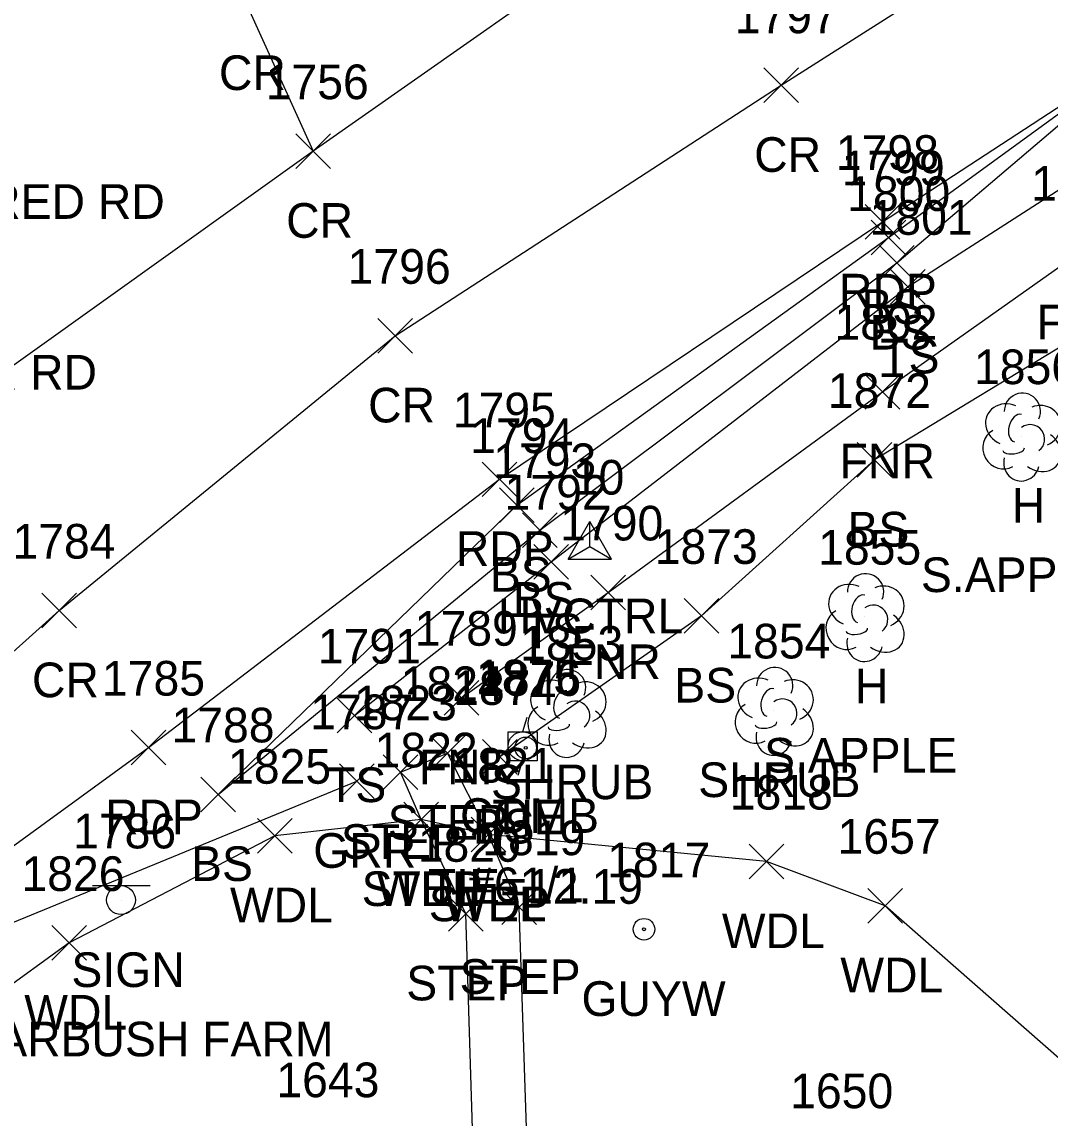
# Model space of a CAD drawing. Extents: x 1647133 to 1649138, y 411736 to 414924.
# Drawn here: x 1649009.1 to 1649068.5, y 412216.1 to 412279.3 of the extents above; entities that cross this region are included whole.
import ezdxf

# ---------------------------------------------------------------- set-up
doc = ezdxf.new("R2010")
doc.units = 0
for name, color, linetype in [('C_A', 7, 'Continuous'), ('C_C', 7, 'Continuous'), ('C_I', 7, 'Continuous'), ('CBP', 7, 'Continuous'), ('CPSM', 7, 'Continuous'), ('L_A', 7, 'Continuous'), ('L_C', 7, 'Continuous'), ('L_I', 7, 'Continuous'), ('L_TIC', 7, 'Continuous'), ('LAWA', 7, 'Continuous'), ('LBF', 7, 'Continuous'), ('LELB', 7, 'Continuous'), ('LFNC', 7, 'Continuous'), ('LSH', 7, 'Continuous'), ('LTD', 7, 'Continuous'), ('P_A', 7, 'Continuous'), ('P_I', 7, 'Continuous'), ('P_TIC', 7, 'Continuous'), ('PET', 7, 'Continuous'), ('PRC', 7, 'Continuous'), ('R_A', 7, 'Continuous'), ('R_I', 7, 'Continuous'), ('R_TIC', 7, 'Continuous'), ('RGR', 7, 'Continuous'), ('S_A', 7, 'Continuous'), ('S_C', 7, 'Continuous'), ('S_I', 7, 'Continuous'), ('SSGN', 7, 'Continuous'), ('U_A', 7, 'Continuous'), ('U_C', 7, 'Continuous'), ('U_I', 7, 'Continuous'), ('UP', 7, 'Continuous'), ('UPGW', 7, 'Continuous')]:
    doc.layers.add(name, color=color, linetype=linetype)

msp = doc.modelspace()

# ---------------------------------------------------------------- linework, layer by layer
at = {"layer": 'CBP'}
for radius in [0.625, 0.0833]:
    msp.add_circle((1649038.192, 412237.421), radius, dxfattribs=at)
at = {"layer": 'CPSM'}
for p, q in [((1649040.642, 412248.315), (1649041.892, 412250.48)), ((1649040.642, 412248.315), (1649041.892, 412250.48)), ((1649040.642, 412248.315), (1649041.892, 412250.48)), ((1649040.642, 412248.315), (1649041.892, 412250.48)), ((1649040.642, 412248.315), (1649041.892, 412250.48)), ((1649043.142, 412248.315), (1649041.892, 412250.48)), ((1649041.892, 412249.036), (1649041.892, 412250.48)), ((1649043.142, 412248.315), (1649041.892, 412250.48)), ((1649041.892, 412249.036), (1649041.892, 412250.48)), ((1649043.142, 412248.315), (1649041.892, 412250.48)), ((1649041.892, 412249.036), (1649041.892, 412250.48)), ((1649043.142, 412248.315), (1649041.892, 412250.48)), ((1649041.892, 412249.036), (1649041.892, 412250.48)), ((1649043.142, 412248.315), (1649041.892, 412250.48)), ((1649041.892, 412249.036), (1649041.892, 412250.48)), ((1649040.642, 412248.315), (1649041.892, 412249.036)), ((1649040.642, 412248.315), (1649041.892, 412249.036)), ((1649040.642, 412248.315), (1649041.892, 412249.036)), ((1649040.642, 412248.315), (1649041.892, 412249.036)), ((1649040.642, 412248.315), (1649041.892, 412249.036)), ((1649041.892, 412249.036), (1649041.892, 412249.036)), ((1649041.892, 412249.036), (1649043.142, 412248.315)), ((1649041.892, 412249.036), (1649041.892, 412249.036)), ((1649041.892, 412249.036), (1649043.142, 412248.315)), ((1649041.892, 412249.036), (1649041.892, 412249.036)), ((1649041.892, 412249.036), (1649043.142, 412248.315)), ((1649041.892, 412249.036), (1649041.892, 412249.036)), ((1649041.892, 412249.036), (1649043.142, 412248.315)), ((1649041.892, 412249.036), (1649041.892, 412249.036)), ((1649041.892, 412249.036), (1649043.142, 412248.315)), ((1649040.642, 412248.315), (1649043.142, 412248.315)), ((1649040.642, 412248.315), (1649043.142, 412248.315)), ((1649040.642, 412248.315), (1649043.142, 412248.315)), ((1649040.642, 412248.315), (1649043.142, 412248.315)), ((1649040.642, 412248.315), (1649043.142, 412248.315))]:
    msp.add_line(p, q, dxfattribs=at)
at = {"layer": 'L_TIC'}
for points in [[(1649058.127, 412265.88), (1649060.127, 412267.88)], [(1649060.127, 412265.88), (1649058.127, 412267.88)], [(1649058.603, 412264.407), (1649060.603, 412266.407)], [(1649060.603, 412264.407), (1649058.603, 412266.407)], [(1649059.245, 412263.03), (1649061.245, 412265.03)], [(1649061.245, 412263.03), (1649059.245, 412265.03)], [(1649057.778, 412256.973), (1649059.778, 412258.973)], [(1649059.778, 412256.973), (1649057.778, 412258.973)], [(1649057.324, 412253.04), (1649059.324, 412255.04)], [(1649059.324, 412253.04), (1649057.324, 412255.04)], [(1649036.681, 412250.434), (1649038.681, 412252.434)], [(1649038.681, 412250.434), (1649036.681, 412252.434)], [(1649038.003, 412248.987), (1649040.003, 412250.987)], [(1649040.003, 412248.987), (1649038.003, 412250.987)], [(1649038.666, 412247.165), (1649040.666, 412249.165)], [(1649040.666, 412247.165), (1649038.666, 412249.165)], [(1649041.96, 412245.39), (1649043.96, 412247.39)], [(1649043.96, 412245.39), (1649041.96, 412247.39)], [(1649047.329, 412244.036), (1649049.329, 412246.036)], [(1649049.329, 412244.036), (1649047.329, 412246.036)], [(1649033.487, 412239.315), (1649035.487, 412241.315)], [(1649035.487, 412239.315), (1649033.487, 412241.315)], [(1649027.319, 412238.289), (1649029.319, 412240.289)], [(1649029.319, 412238.289), (1649027.319, 412240.289)], [(1649032.671, 412236.119), (1649034.671, 412238.119)], [(1649034.671, 412236.119), (1649032.671, 412238.119)], [(1649032.671, 412236.119), (1649034.671, 412238.119)], [(1649034.671, 412236.119), (1649032.671, 412238.119)], [(1649035.698, 412235.9), (1649037.698, 412237.9)], [(1649037.698, 412235.9), (1649035.698, 412237.9)], [(1649029.965, 412235.013), (1649031.965, 412237.013)], [(1649031.965, 412235.013), (1649029.965, 412237.013)], [(1649019.44, 412233.736), (1649021.44, 412235.736)], [(1649021.44, 412233.736), (1649019.44, 412235.736)], [(1649019.44, 412233.736), (1649021.44, 412235.736)], [(1649021.44, 412233.736), (1649019.44, 412235.736)], [(1649031.165, 412232.292), (1649033.165, 412234.292)], [(1649033.165, 412232.292), (1649031.165, 412234.292)], [(1649031.165, 412232.292), (1649033.165, 412234.292)], [(1649033.165, 412232.292), (1649031.165, 412234.292)], [(1649022.706, 412231.35), (1649024.706, 412233.35)], [(1649024.706, 412231.35), (1649022.706, 412233.35)], [(1649035.041, 412231.414), (1649037.041, 412233.414)], [(1649037.041, 412231.414), (1649035.041, 412233.414)], [(1649035.041, 412231.414), (1649037.041, 412233.414)], [(1649037.041, 412231.414), (1649035.041, 412233.414)], [(1649051.095, 412229.86), (1649053.095, 412231.86)], [(1649053.095, 412229.86), (1649051.095, 412231.86)], [(1649036.817, 412227.224), (1649038.817, 412229.224)], [(1649038.817, 412227.224), (1649036.817, 412229.224)], [(1649057.93, 412227.309), (1649059.93, 412229.309)], [(1649059.93, 412227.309), (1649057.93, 412229.309)], [(1649033.74, 412226.846), (1649035.74, 412228.846)], [(1649035.74, 412226.846), (1649033.74, 412228.846)], [(1649010.835, 412225.16), (1649012.835, 412227.16)], [(1649012.835, 412225.16), (1649010.835, 412227.16)]]:
    msp.add_lwpolyline(points, dxfattribs=at)
at = {"layer": 'LAWA'}
msp.add_lwpolyline([(1649111.119, 412178.299), (1649089.042, 412199.035), (1649075.25, 412213.993), (1649058.93, 412228.309), (1649052.095, 412230.86), (1649036.041, 412232.414), (1649032.165, 412233.292), (1649023.706, 412232.35), (1649011.835, 412226.16), (1649003.248, 412219.943), (1648994.704, 412211.046)], dxfattribs=at)
at = {"layer": 'LBF'}
for points in [[(1649035.394, 412205.124), (1649035.268, 412210.483), (1649034.74, 412227.846), (1649032.165, 412233.292), (1649030.965, 412236.013), (1649033.671, 412237.119)], [(1649035.394, 412205.124), (1649038.481, 412205.146), (1649038.43, 412209.721), (1649037.817, 412228.224), (1649036.041, 412232.414), (1649033.671, 412237.119)]]:
    msp.add_lwpolyline(points, dxfattribs=at)
at = {"layer": 'LELB'}
for points in [[(1649020.44, 412234.736), (1649037.681, 412251.434), (1649059.127, 412266.88), (1649074.295, 412277.904)], [(1649020.44, 412234.736), (1649039.003, 412249.987), (1649059.603, 412265.407), (1649074.295, 412277.904)], [(1649028.319, 412239.289), (1649039.666, 412248.165), (1649060.245, 412264.03), (1649074.144, 412272.961), (1649081.145, 412265.519)], [(1649131.201, 412223.069), (1649106.638, 412242.921), (1649089.809, 412258.031), (1649081.131, 412263.74), (1649071.005, 412261.74), (1649058.324, 412254.04), (1649048.329, 412245.036), (1649036.698, 412236.9)]]:
    msp.add_lwpolyline(points, dxfattribs=at)
at = {"layer": 'LFNC'}
msp.add_lwpolyline([(1649034.487, 412240.315), (1649042.96, 412246.39), (1649058.778, 412257.973), (1649070.137, 412265.992), (1649075.318, 412269.647)], dxfattribs=at)
at = {"layer": 'LSH'}
for p, q in [((1649040.563, 412239.458), (1649040.563, 412239.458)), ((1649040.563, 412239.458), (1649040.563, 412239.458)), ((1649052.52, 412239.58), (1649052.52, 412239.58)), ((1649052.52, 412239.58), (1649052.52, 412239.58))]:
    msp.add_line(p, q, dxfattribs=at)
for centre in [(1649040.609, 412240.892), (1649052.567, 412241.014)]:
    msp.add_arc(centre, 1.047, 335.52715, 180.95627, dxfattribs=at)
for centre, major_axis, ratio, start_param, end_param in [((1649039.771, 412240.125), (1.21, -0.512), 0.895232, 1.570796, 4.712389), ((1649041.604, 412240.042), (-1.141, -0.483), 0.949671, 1.570796, 4.712389), ((1649051.728, 412240.246), (1.21, -0.512), 0.895232, 1.570796, 4.712389), ((1649053.562, 412240.163), (-1.141, -0.483), 0.949671, 1.570796, 4.712389), ((1649040.354, 412239.917), (-0.208, -0.792), 0.645439, 3.141593, 6.283185), ((1649052.312, 412240.038), (-0.208, -0.792), 0.645439, 3.141593, 6.283185), ((1649039.479, 412238.75), (0.584, -1.042), 0.959034, 3.141593, 6.283185), ((1649041.063, 412239.292), (-0.5, 0.667), 0.989748, 3.141593, 6.283185), ((1649051.437, 412238.871), (0.584, -1.042), 0.959034, 3.141593, 6.283185), ((1649053.02, 412239.413), (-0.5, 0.667), 0.989748, 3.141593, 6.283185), ((1649041.563, 412238.625), (-1.09, 0.792), 0.841452, 1.570796, 4.712389), ((1649053.52, 412238.747), (-1.09, 0.792), 0.841452, 1.570796, 4.712389), ((1649040.104, 412238.708), (-0.625, -0.083), 0.423636, 0, 3.141593), ((1649052.062, 412238.83), (-0.625, -0.083), 0.423636, 0, 3.141593), ((1649040.563, 412237.958), (0.265, 1.061), 0.942809, 1.570796, 4.712389), ((1649052.52, 412238.08), (0.265, 1.061), 0.942809, 1.570796, 4.712389)]:
    msp.add_ellipse(centre, major_axis=major_axis, ratio=ratio, start_param=start_param, end_param=end_param, dxfattribs=at)
at = {"layer": 'LTD'}
for p, q in [((1649066.812, 412255.411), (1649066.812, 412255.411)), ((1649066.812, 412255.411), (1649066.812, 412255.411)), ((1649057.761, 412244.992), (1649057.761, 412244.992)), ((1649057.761, 412244.992), (1649057.761, 412244.992))]:
    msp.add_line(p, q, dxfattribs=at)
for centre in [(1649066.859, 412256.845), (1649057.807, 412246.426)]:
    msp.add_arc(centre, 1.047, 335.52715, 180.95627, dxfattribs=at)
for centre, major_axis, ratio, start_param, end_param in [((1649066.02, 412256.077), (1.21, -0.512), 0.895232, 1.570796, 4.712389), ((1649067.854, 412255.994), (-1.141, -0.483), 0.949671, 1.570796, 4.712389), ((1649066.604, 412255.869), (-0.208, -0.792), 0.645439, 3.141593, 6.283185), ((1649065.729, 412254.702), (0.584, -1.042), 0.959034, 3.141593, 6.283185), ((1649067.312, 412255.244), (-0.5, 0.667), 0.989748, 3.141593, 6.283185), ((1649067.812, 412254.578), (-1.09, 0.792), 0.841452, 1.570796, 4.712389), ((1649066.354, 412254.661), (-0.625, -0.083), 0.423636, 0, 3.141593), ((1649066.813, 412253.911), (0.265, 1.061), 0.942809, 1.570796, 4.712389), ((1649056.969, 412245.658), (1.21, -0.512), 0.895232, 1.570796, 4.712389), ((1649058.802, 412245.575), (-1.141, -0.483), 0.949671, 1.570796, 4.712389), ((1649057.552, 412245.45), (-0.208, -0.792), 0.645439, 3.141593, 6.283185), ((1649058.261, 412244.825), (-0.5, 0.667), 0.989748, 3.141593, 6.283185), ((1649056.677, 412244.283), (0.584, -1.042), 0.959034, 3.141593, 6.283185), ((1649058.761, 412244.158), (-1.09, 0.792), 0.841452, 1.570796, 4.712389), ((1649057.302, 412244.242), (-0.625, -0.083), 0.423636, 0, 3.141593), ((1649057.761, 412243.492), (0.265, 1.061), 0.942809, 1.570796, 4.712389)]:
    msp.add_ellipse(centre, major_axis=major_axis, ratio=ratio, start_param=start_param, end_param=end_param, dxfattribs=at)
at = {"layer": 'P_TIC'}
for points in [[(1649051.944, 412274.662), (1649053.944, 412276.662)], [(1649053.944, 412274.662), (1649051.944, 412276.662)], [(1649024.933, 412270.858), (1649026.933, 412272.858)], [(1649026.933, 412270.858), (1649024.933, 412272.858)], [(1649024.933, 412270.858), (1649026.933, 412272.858)], [(1649026.933, 412270.858), (1649024.933, 412272.858)], [(1649057.783, 412266.778), (1649059.783, 412268.778)], [(1649059.783, 412266.778), (1649057.783, 412268.778)], [(1649029.664, 412260.202), (1649031.664, 412262.202)], [(1649031.664, 412260.202), (1649029.664, 412262.202)], [(1649035.674, 412251.918), (1649037.674, 412253.918)], [(1649037.674, 412251.918), (1649035.674, 412253.918)], [(1649010.263, 412244.342), (1649012.263, 412246.342)], [(1649012.263, 412244.342), (1649010.263, 412246.342)], [(1649015.429, 412236.436), (1649017.429, 412238.436)], [(1649017.429, 412236.436), (1649015.429, 412238.436)]]:
    msp.add_lwpolyline(points, dxfattribs=at)
at = {"layer": 'PET'}
msp.add_lwpolyline([(1648998.767, 412333.423), (1648994.313, 412324.566), (1648993.834, 412315.066), (1649000.687, 412300.559), (1649003.42, 412288.198), (1649004.904, 412270.19), (1649001.609, 412254.477), (1648993.905, 412243.995), (1648984.626, 412233.464), (1648979.622, 412228.916), (1648985.327, 412222.555), (1648990.487, 412216.934), (1649002.33, 412227.191), (1649016.429, 412237.436), (1649036.674, 412252.918), (1649058.783, 412267.778), (1649074.295, 412277.904), (1649090.06, 412287.47)], dxfattribs=at)
at = {"layer": 'PRC'}
for points in [[(1648967.33, 412365.005), (1648986.07, 412339.485), (1648994.313, 412324.566), (1649012.579, 412298.018), (1649022.055, 412280.385), (1649025.933, 412271.858), (1649001.609, 412254.477)], [(1648985.327, 412222.555), (1648998.031, 412233.463), (1649011.263, 412245.342), (1649030.664, 412261.202), (1649052.944, 412275.662), (1649084.878, 412295.987)], [(1649046.681, 412286.417), (1649025.933, 412271.858)]]:
    msp.add_lwpolyline(points, dxfattribs=at)
at = {"layer": 'R_TIC'}
for points in [[(1649027.445, 412234.497), (1649029.445, 412236.497)], [(1649029.445, 412234.497), (1649027.445, 412236.497)]]:
    msp.add_lwpolyline(points, dxfattribs=at)
at = {"layer": 'RGR'}
msp.add_lwpolyline([(1648992.163, 412217.871), (1649000.802, 412224.157), (1649028.445, 412235.497)], dxfattribs=at)
at = {"layer": 'SSGN'}
for p, q in [((1649013.189, 412229.471), (1649016.522, 412229.471)), ((1649014.836, 412228.637), (1649014.836, 412228.637))]:
    msp.add_line(p, q, dxfattribs=at)
msp.add_circle((1649014.836, 412228.637), 0.833, dxfattribs=at)
at = {"layer": 'UP'}
for p, q in [((1649038.264, 412239.178), (1649038.014, 412238.345)), ((1649037.181, 412236.678), (1649037.181, 412238.345)), ((1649037.181, 412238.345), (1649038.847, 412238.345)), ((1649038.847, 412238.345), (1649038.847, 412236.678)), ((1649038.014, 412237.511), (1649038.014, 412237.511)), ((1649038.847, 412236.678), (1649037.181, 412236.678)), ((1649037.764, 412235.845), (1649038.014, 412236.678))]:
    msp.add_line(p, q, dxfattribs=at)
msp.add_circle((1649038.014, 412237.511), 0.833, dxfattribs=at)
at = {"layer": 'UPGW'}
for radius in [0.625, 0.0833]:
    msp.add_circle((1649045.018, 412226.948), radius, dxfattribs=at)

# ---------------------------------------------------------------- texts
at = {"layer": 'C_A'}
for s, p in [('HVCTRL', (1649036.585, 412244.036)), ('HVCTRL', (1649036.585, 412244.036)), ('HVCTRL', (1649036.585, 412244.036)), ('HVCTRL', (1649036.585, 412244.036)), ('HVCTRL', (1649036.585, 412244.036)), ('TIE', (1649036.271, 412232.421))]:
    msp.add_text(s, height=2, dxfattribs=at).set_placement(p)
at = {"layer": 'C_C'}
msp.add_text('TIE=12.19', height=2, dxfattribs=at).set_placement((1649032.546, 412228.421))
at = {"layer": 'C_I'}
for s, p in [('10', (1649040.908, 412252.036)), ('10', (1649040.908, 412252.036)), ('10', (1649040.908, 412252.036)), ('10', (1649040.908, 412252.036)), ('10', (1649040.908, 412252.036)), ('1876', (1649035.444, 412240.421))]:
    msp.add_text(s, height=2, dxfattribs=at).set_placement(p)
at = {"layer": 'L_A'}
for s, p in [('BS', (1649057.568, 412261.88)), ('FNR', (1649067.673, 412260.992)), ('BS', (1649058.044, 412260.407)), ('TS', (1649058.654, 412259.03)), ('FNR', (1649056.313, 412252.973)), ('H', (1649066.245, 412250.411)), ('BS', (1649056.765, 412249.04)), ('BS', (1649036.122, 412246.434)), ('BS', (1649037.444, 412244.987)), ('TS', (1649038.076, 412243.165)), ('FNR', (1649040.496, 412241.39)), ('BS', (1649046.769, 412240.036)), ('H', (1649057.194, 412239.992)), ('FNR', (1649032.022, 412235.315)), ('SHRUB', (1649048.15, 412234.58)), ('TS', (1649026.728, 412234.289)), ('SHRUB', (1649036.193, 412234.458)), ('STEP', (1649030.23, 412232.119)), ('STEP', (1649030.23, 412232.119)), ('BS', (1649035.139, 412231.9)), ('STEP', (1649027.524, 412231.013)), ('BS', (1649018.88, 412229.736)), ('BS', (1649018.88, 412229.736)), ('STEP', (1649028.724, 412228.292)), ('WDL', (1649029.582, 412228.292)), ('WDL', (1649021.123, 412227.35)), ('STEP', (1649032.6, 412227.414)), ('WDL', (1649033.458, 412227.414)), ('WDL', (1649049.512, 412225.86)), ('STEP', (1649034.376, 412223.224)), ('WDL', (1649056.348, 412223.309)), ('STEP', (1649031.3, 412222.846)), ('WDL', (1649009.252, 412221.16))]:
    msp.add_text(s, height=2, dxfattribs=at).set_placement(p)
at = {"layer": 'L_C'}
for p in [(1649061.001, 412246.411), (1649051.95, 412235.992)]:
    msp.add_text('S.APPLE', height=2, dxfattribs=at).set_placement(p)
at = {"layer": 'L_I'}
for s, p in [('1799', (1649056.426, 412269.88)), ('1803', (1649067.365, 412268.992)), ('1800', (1649056.745, 412268.407)), ('1801', (1649058.04, 412267.03)), ('1802', (1649056.006, 412260.973)), ('1856', (1649064.064, 412258.411)), ('1872', (1649055.631, 412257.04)), ('1794', (1649034.988, 412254.434)), ('1793', (1649036.31, 412252.987)), ('1792', (1649036.974, 412251.165)), ('1790', (1649040.181, 412249.39)), ('1873', (1649045.636, 412248.036)), ('1855', (1649055.068, 412247.992)), ('1789', (1649031.786, 412243.315)), ('1791', (1649026.193, 412242.289)), ('1853', (1649037.87, 412242.458)), ('1854', (1649049.827, 412242.58)), ('1824', (1649030.978, 412240.119)), ('1824', (1649030.978, 412240.119)), ('1874', (1649034.005, 412239.9)), ('1823', (1649028.272, 412239.013)), ('1788', (1649017.747, 412237.736)), ('1788', (1649017.747, 412237.736)), ('1822', (1649029.472, 412236.292)), ('1822', (1649029.472, 412236.292)), ('1825', (1649021.013, 412235.35)), ('1821', (1649033.915, 412235.414)), ('1821', (1649033.915, 412235.414)), ('1818', (1649049.969, 412233.86)), ('1820', (1649031.961, 412230.846)), ('1819', (1649035.683, 412231.224)), ('1657', (1649056.19, 412231.309)), ('1826', (1649009.087, 412229.16)), ('1643', (1649023.8, 412217.258)), ('1650', (1649053.453, 412216.622))]:
    msp.add_text(s, height=2, dxfattribs=at).set_placement(p)
at = {"layer": 'P_A'}
for s, p in [('CR', (1649020.488, 412275.385)), ('CR', (1649051.377, 412270.662)), ('CR', (1649024.366, 412266.858)), ('CR', (1649024.366, 412266.858)), ('RDP', (1649056.271, 412262.778)), ('CR', (1649029.097, 412256.202)), ('RDP', (1649034.162, 412247.918)), ('CR', (1649009.696, 412240.342)), ('RDP', (1649013.917, 412232.436))]:
    msp.add_text(s, height=2, dxfattribs=at).set_placement(p)
at = {"layer": 'P_I'}
for s, p in [('1797', (1649050.251, 412278.662)), ('1756', (1649023.185, 412274.858)), ('1756', (1649023.185, 412274.858)), ('1798', (1649056.09, 412270.778)), ('1796', (1649027.916, 412264.202)), ('1795', (1649033.981, 412255.918)), ('1784', (1649008.57, 412248.342)), ('1785', (1649013.736, 412240.436))]:
    msp.add_text(s, height=2, dxfattribs=at).set_placement(p)
at = {"layer": 'R_A'}
msp.add_text('GRR', height=2, dxfattribs=at).set_placement((1649025.933, 412230.497))
at = {"layer": 'R_I'}
msp.add_text('1787', height=2, dxfattribs=at).set_placement((1649025.752, 412238.497))
at = {"layer": 'S_A'}
msp.add_text('SIGN', height=2, dxfattribs=at).set_placement((1649011.974, 412223.617))
at = {"layer": 'S_C'}
for s, p in [('STOP & TAFTSVILLE COVERED RD', (1648972.483, 412267.952)), ('QUECHEE MAIN ST & RIVER RD', (1648972.587, 412258.098)), ('SUGARBUSH FARM', (1649001.84, 412219.617))]:
    msp.add_text(s, height=2, dxfattribs=at).set_placement(p)
at = {"layer": 'S_I'}
msp.add_text('1786', height=2, dxfattribs=at).set_placement((1649012.068, 412231.617))
at = {"layer": 'U_A'}
for s, p in [('COMB', (1649034.4, 412232.511)), ('GUYW', (1649041.412, 412221.948))]:
    msp.add_text(s, height=2, dxfattribs=at).set_placement(p)
at = {"layer": 'U_C'}
msp.add_text('#61/1', height=2, dxfattribs=at).set_placement((1649034.865, 412228.511))
at = {"layer": 'U_I'}
for s, p in [('1875', (1649035.321, 412240.511)), ('1817', (1649042.892, 412229.948))]:
    msp.add_text(s, height=2, dxfattribs=at).set_placement(p)

doc.saveas('drawing.dxf')
